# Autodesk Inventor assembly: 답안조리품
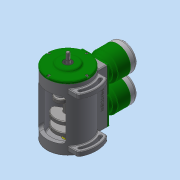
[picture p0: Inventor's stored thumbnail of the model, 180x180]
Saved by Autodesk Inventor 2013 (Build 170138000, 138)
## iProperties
Created: 2017-08
Part Number: 답안조리품
Document SubType Name: Assembly
Designer: dgall
Author: dgall
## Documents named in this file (16)
- C:\Users\dgall\Desktop\370807V1004\답안조리품.iam
- C:\Users\dgall\Desktop\370807V1004\본체.ipt
- C:\Users\dgall\Desktop\370807V1004\실린더.ipt
- C:\Users\dgall\Desktop\370807V1004\실린더헤드.ipt
- C:\Users\dgall\Desktop\370807V1004\볼트 M5 x 20.ipt
- C:\Users\dgall\Desktop\370807V1004\앞커버.ipt
- C:\Users\dgall\Desktop\370807V1004\베어링 12 x 28 x 8.ipt
- C:\Users\dgall\Desktop\370807V1004\오일 실 12 25 7.ipt
- C:\Users\dgall\Desktop\370807V1004\볼트 M4 x 8.ipt
- C:\Users\dgall\Desktop\370807V1004\크랭크축.ipt
- C:\Users\dgall\Desktop\370807V1004\커넥팅로드 엔드.ipt
- C:\Users\dgall\Desktop\370807V1004\커넥팅로드.ipt
- C:\Users\dgall\Desktop\370807V1004\피스톤.ipt
- C:\Users\dgall\Desktop\370807V1004\피스톤핀.ipt
- C:\Users\dgall\Desktop\370807V1004\너트 M4.ipt
- C:\Users\dgall\Desktop\370807V1004\육각 머리 볼트 M4 x 16.ipt
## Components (4 placed, 2 different names)
1. 피스톤:1
2. 피스톤핀:1
3. 피스톤:2
4. 피스톤핀:2
